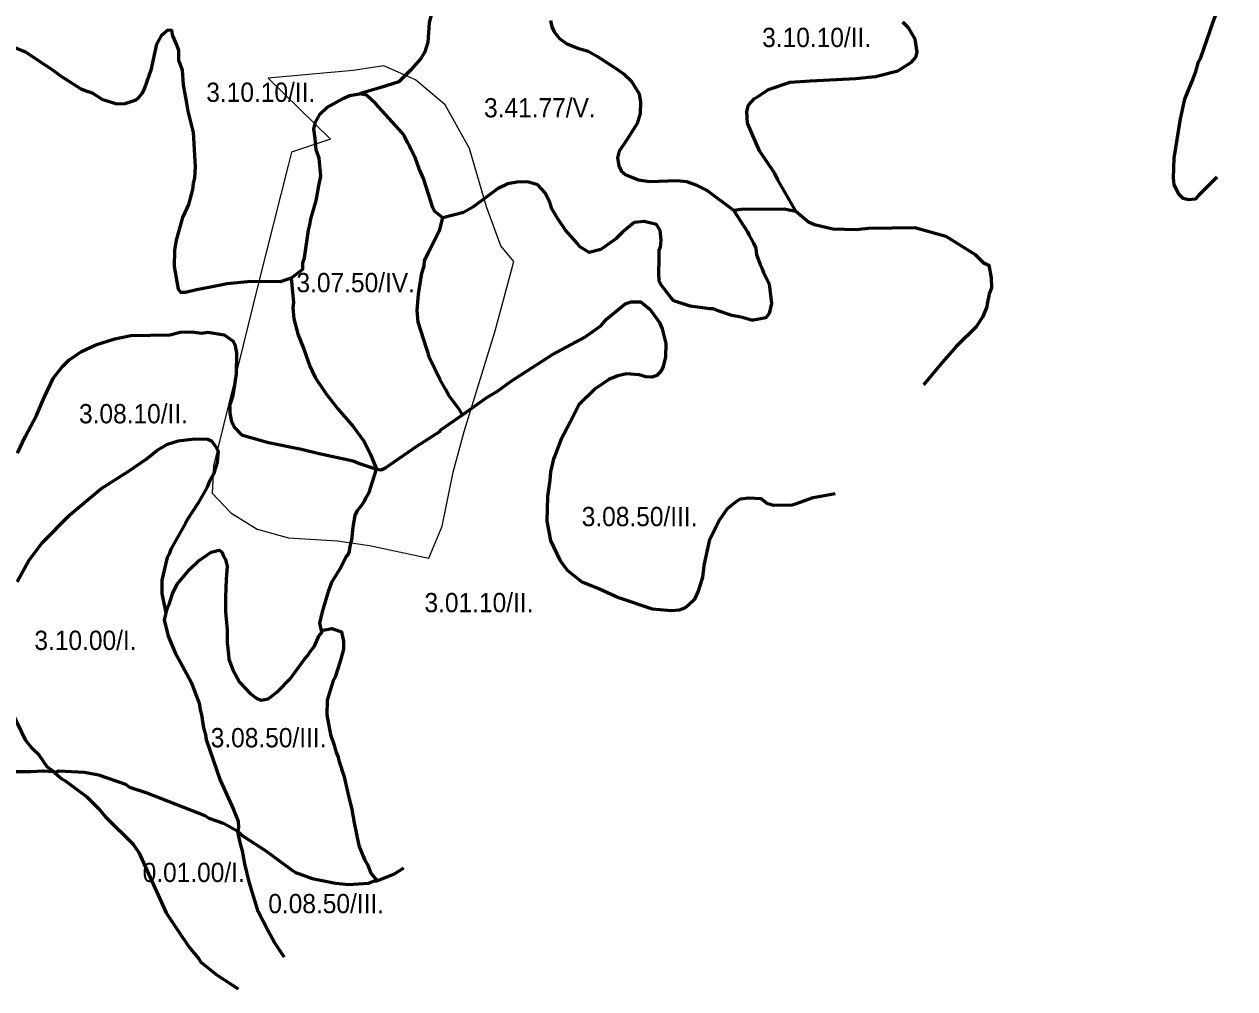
# Model space of a CAD drawing. Extents: x -555506 to -553028, y -1186750 to -1182668.
# Drawn here: x -554397 to -553142, y -1186750 to -1185749 of the extents above; entities that cross this region are included whole.
import ezdxf
from ezdxf.enums import TextEntityAlignment as Align

# ---------------------------------------------------------------- set-up
doc = ezdxf.new("R2010")
doc.units = 0
doc.header["$LTSCALE"] = 8
doc.layers.add('21', color=7, linetype='Continuous', lineweight=53)
doc.layers.add('41', color=7, linetype='Continuous', lineweight=25)
doc.layers.add('22', color=7, linetype='Continuous')

msp = doc.modelspace()

# ---------------------------------------------------------------- linework, layer by layer
at = {"layer": '21'}
msp.add_line((-554365.314, -1186526.02), (-554366.937, -1186524.625), dxfattribs=at)
for points in [[(-553945.125, -1185676.626), (-553945.937, -1185701.626), (-553947.625, -1185708.376), (-553952.75, -1185718.625), (-553963.75, -1185728.75), (-553971.375, -1185733.876), (-553974.375, -1185737.25), (-553977.312, -1185747.375), (-553978.625, -1185767.751), (-553981.562, -1185778), (-553985.812, -1185784.751), (-553996.375, -1185796.625), (-554003.187, -1185803.376), (-554008.687, -1185808.875), (-554027.375, -1185814.876), (-554049.375, -1185821.626)], [(-553160.224, -1185907.948), (-553179, -1185926.75), (-553182.812, -1185930.625), (-553189.562, -1185931.5), (-553195.062, -1185930.125), (-553199.75, -1185925.501), (-553204.437, -1185915.376), (-553205.25, -1185908.5), (-553204.437, -1185888.25), (-553198.062, -1185847.5), (-553193.375, -1185827.126), (-553185.75, -1185808.501), (-553181.937, -1185798.25), (-553179.375, -1185788.125), (-553177.312, -1185784.751), (-553163.687, -1185745.75), (-553151, -1185711.875), (-553145.5, -1185700.001), (-553141.687, -1185689.376)], [(-554120.187, -1186012.876), (-554131.625, -1186016.626), (-554162.187, -1186016.25), (-554186.75, -1186018.751), (-554204.125, -1186022.125), (-554218.562, -1186024.75), (-554230, -1186027.625), (-554234.687, -1186027.625), (-554237.25, -1186024.25), (-554241.437, -1186000.5), (-554241.062, -1185983.626), (-554239.375, -1185973.376), (-554232.562, -1185949.625), (-554226.625, -1185936.126), (-554222.375, -1185920.875), (-554221.562, -1185914.001), (-554220.25, -1185909.001), (-554219.437, -1185897.125), (-554221.562, -1185861.501), (-554227.062, -1185839.376), (-554228.75, -1185829.251), (-554232.125, -1185812.251), (-554233, -1185797.001), (-554236.812, -1185786.876), (-554236.812, -1185776.625), (-554239.375, -1185769.876), (-554243.187, -1185761.376), (-554244, -1185755.875), (-554248.25, -1185755.501), (-554255.062, -1185761.376), (-554260.125, -1185769.876), (-554266.062, -1185797.001), (-554272.437, -1185815.751), (-554274.937, -1185820.751), (-554279.187, -1185825.876), (-554281.312, -1185828.001), (-554292.75, -1185831.751), (-554301.25, -1185832.251), (-554315.687, -1185827.626), (-554326.25, -1185820.751), (-554333.875, -1185818.25), (-554338.125, -1185816.501), (-554359.312, -1185803), (-554366.125, -1185797.876), (-554395.375, -1185778.376), (-554422.937, -1185767.375)], [(-553851.375, -1185745.25), (-553850.125, -1185752.125), (-553847.562, -1185757.126), (-553842.062, -1185764.001), (-553834.437, -1185769.5), (-553823, -1185774.126), (-553812.375, -1185777.126), (-553802.625, -1185782.626), (-553786.937, -1185792.751), (-553775.062, -1185801.25), (-553767.875, -1185808.001), (-553759.375, -1185821.626), (-553758.125, -1185830.126), (-553758.562, -1185842), (-553761.5, -1185852.125), (-553772.125, -1185869.125), (-553780.187, -1185881.001), (-553781.875, -1185887.75), (-553780.625, -1185896.25), (-553778.062, -1185901.375), (-553773.375, -1185905.625), (-553760.25, -1185910.626), (-553748.812, -1185912.376), (-553720.375, -1185911.5), (-553710.25, -1185912.376), (-553700.5, -1185915.75), (-553689, -1185921.625), (-553661.437, -1185942.001)], [(-553597, -1185943.25), (-553615.687, -1185910.626), (-553618.625, -1185904.25), (-553634.75, -1185880.501), (-553647.062, -1185851.75), (-553647.875, -1185839.875), (-553646.187, -1185833.125), (-553639.812, -1185826.25), (-553636.875, -1185824.625), (-553625.437, -1185817.001), (-553602.937, -1185809.375), (-553581.75, -1185808.001), (-553534.687, -1185805.5), (-553514.375, -1185803.376), (-553491, -1185797.5), (-553487.187, -1185795.375), (-553477.062, -1185788.501), (-553472.375, -1185783.501), (-553471.125, -1185778.376), (-553473.25, -1185764.876), (-553480, -1185753), (-553485.937, -1185747.001)], [(-554120.187, -1186012.876), (-554108.312, -1186003.501), (-554108.312, -1185996.75), (-554106.625, -1185991.626), (-554102.375, -1185962.751), (-554100.687, -1185956), (-554100.25, -1185952.626), (-554094.375, -1185932.25), (-554091.812, -1185917.001), (-554089.687, -1185906.876), (-554091.375, -1185888.25), (-554094.375, -1185879.75), (-554095.625, -1185867.876), (-554096.875, -1185857.625), (-554095.187, -1185850.876), (-554090.125, -1185842.376), (-554083.312, -1185835.626), (-554066.375, -1185826.25), (-554060, -1185823.376), (-554049.375, -1185821.626)], [(-553962.937, -1185950.125), (-553971.812, -1185943.25), (-553973.5, -1185939.876), (-553983.25, -1185909.375), (-553987.5, -1185899.25), (-553991.75, -1185887.376), (-553996.375, -1185878.876), (-553997.687, -1185875.5), (-553999.812, -1185872.126), (-554002.75, -1185865.251), (-554005.312, -1185861.875), (-554032.875, -1185831.376), (-554042.187, -1185822.876), (-554049.375, -1185821.626)], [(-553661.437, -1185942.001), (-553647.062, -1185964.5), (-553645.75, -1185967.876), (-553640.687, -1185976.376), (-553638.562, -1185981.501), (-553637.75, -1185988.25), (-553633.875, -1185998.375), (-553632.187, -1186001.875), (-553630.5, -1186006.875), (-553624.562, -1186018.751), (-553622.062, -1186039.125), (-553624.562, -1186049.25), (-553628, -1186054), (-553640.687, -1186056.125), (-553642.812, -1186056.125), (-553653.812, -1186053.126), (-553663.187, -1186051.375), (-553677.562, -1186046.751), (-553682.687, -1186044.626), (-553686.062, -1186044.626), (-553706.375, -1186041.626), (-553723.375, -1186036.125), (-553726.75, -1186032.75), (-553736.937, -1186019.251), (-553738.625, -1186015.751), (-553739.062, -1186007.375), (-553738.625, -1185993.751), (-553738.625, -1185983.626), (-553737.375, -1185980.25), (-553736.5, -1185973.376), (-553737.75, -1185963.25), (-553741.625, -1185956.876), (-553754.312, -1185953.875), (-553764.5, -1185955.125), (-553776.812, -1185964.876), (-553783.562, -1185971.75), (-553795.437, -1185980.25), (-553799.25, -1185983.125), (-553811.125, -1185986.125), (-553821.312, -1185979.75), (-553823.875, -1185976.376), (-553835.75, -1185962.751), (-553843.75, -1185951.001), (-553850.125, -1185940.75), (-553852.25, -1185934.001), (-553857.312, -1185923.75), (-553864.562, -1185915.75), (-553875.125, -1185912.751), (-553886.187, -1185913.251), (-553895.5, -1185914.876), (-553906.5, -1185920), (-553931.937, -1185939.126), (-553941.687, -1185944.626), (-553962.937, -1185950.125)], [(-553661.437, -1185942.001), (-553653.812, -1185941.251), (-553608.875, -1185940.75), (-553597, -1185943.25)], [(-553597, -1185943.25), (-553583.875, -1185954.375), (-553577.5, -1185956.876), (-553558.437, -1185961.501), (-553533.875, -1185962.375), (-553521.562, -1185960.75), (-553473.625, -1185960.25), (-553441.437, -1185969.126), (-553410.875, -1185988.25), (-553402.437, -1185996.75), (-553396.875, -1185999.251), (-553394.375, -1186012.376), (-553393.937, -1186022.625), (-553396.5, -1186029.376), (-553398.625, -1186039.501), (-553399, -1186042.501), (-553403.25, -1186053.126), (-553410.062, -1186063.251), (-553430.812, -1186083.625), (-553447.173, -1186102.559), (-553464.42, -1186123.36)], [(-553942.562, -1186154.5), (-553945.5, -1186149.75), (-553957, -1186134.5), (-553960.375, -1186127.751), (-553966.312, -1186117.626), (-553976.875, -1186095.501), (-553978.187, -1186090.376), (-553979.875, -1186085.376), (-553988.75, -1186058.25), (-553989.625, -1186046.375), (-553988.375, -1186029.376), (-553984.937, -1186007.375), (-553982.437, -1185999.75), (-553982, -1185994.625), (-553977.75, -1185986.125), (-553966.312, -1185962.375), (-553962.937, -1185950.125)], [(-554120.187, -1186012.876), (-554118.062, -1186037.876), (-554118.5, -1186043.001), (-554117.687, -1186054.875), (-554113, -1186071.751), (-554107.5, -1186085.376), (-554101.125, -1186104.001), (-554095.625, -1186115.875), (-554084.187, -1186132.875), (-554071.875, -1186148.125), (-554056.187, -1186166.75), (-554044.75, -1186182), (-554037.937, -1186195.626), (-554032, -1186210.876)], [(-553942.562, -1186154.5), (-553917.562, -1186136.625), (-553906.5, -1186129.876), (-553892.125, -1186119.625), (-553849.312, -1186091.751), (-553815.812, -1186073.876), (-553799.25, -1186062), (-553793.312, -1186055.251), (-553773.812, -1186039.501), (-553767.875, -1186037.376), (-553757.687, -1186037.376), (-553747.937, -1186045.126), (-553738.187, -1186058.625), (-553735.687, -1186065.376), (-553731.875, -1186080.625), (-553732.25, -1186094.25), (-553734.375, -1186104.375), (-553736.937, -1186109.5), (-553741.187, -1186113.75), (-553746.25, -1186115.501), (-553752.625, -1186115), (-553759.375, -1186112.875), (-553772.562, -1186112.001), (-553781.437, -1186114.126), (-553790.75, -1186118), (-553805.187, -1186127.375), (-553822.125, -1186144.251), (-553827.25, -1186154.5), (-553830.625, -1186161.251), (-553840.375, -1186179.876), (-553846.75, -1186196.875), (-553848.437, -1186200.251), (-553851.375, -1186213.751), (-553852.25, -1186222.251), (-553854.375, -1186239.25), (-553855.25, -1186264.626), (-553851.375, -1186285), (-553841.625, -1186305.376), (-553834, -1186315.5), (-553818.75, -1186327.876), (-553800.5, -1186335.125), (-553781, -1186344), (-553745.812, -1186355.875), (-553726.312, -1186357.5), (-553717.437, -1186356.626), (-553711.937, -1186354.625), (-553708.125, -1186351.625), (-553701.312, -1186344.876), (-553698.375, -1186338.001), (-553693.25, -1186322.751), (-553692, -1186310.875), (-553686.062, -1186283.75), (-553679.687, -1186270.251), (-553676.312, -1186264.25), (-553667.812, -1186251.5), (-553657.625, -1186243.876), (-553654.25, -1186241.751), (-553645.75, -1186240.5), (-553633.062, -1186241.375), (-553627.125, -1186246.001), (-553619.937, -1186248.126), (-553600.812, -1186247.75), (-553596.187, -1186246.501), (-553578.812, -1186240.126), (-553556.1, -1186236.222)], [(-554404.25, -1186194.25), (-554396.187, -1186177.375), (-554384.375, -1186155.25), (-554376.687, -1186136.625), (-554366.937, -1186116.251), (-554360.187, -1186107.751), (-554357.625, -1186104.375), (-554350.875, -1186097.626), (-554337.687, -1186088.75), (-554322.875, -1186082), (-554303.375, -1186075.625), (-554286.812, -1186072.251), (-554246.125, -1186071.375), (-554235.5, -1186068.75), (-554223.25, -1186068.375), (-554213.062, -1186069.626), (-554206.687, -1186068.75), (-554189.75, -1186071.375), (-554180.437, -1186078.126), (-554178.687, -1186081.5), (-554177, -1186090), (-554177.437, -1186112.001), (-554179.562, -1186125.626), (-554181.25, -1186135.751), (-554184.25, -1186145.125), (-554183.812, -1186147.625), (-554183.812, -1186152.751), (-554182.125, -1186161.251), (-554178.687, -1186168.001), (-554171.937, -1186175.25), (-554143.937, -1186183.25), (-554109.625, -1186190.126), (-554091.375, -1186194.75), (-554056.187, -1186202.376), (-554049.375, -1186204.875), (-554032, -1186210.876)], [(-554032, -1186210.876), (-554026.937, -1186211.626), (-554022.687, -1186209.625), (-553990.062, -1186187.126), (-553966.312, -1186171.875), (-553965.062, -1186170.126), (-553942.562, -1186154.5)], [(-554404.687, -1186327.876), (-554392.375, -1186305.751), (-554378.437, -1186287.125), (-554350, -1186258.375), (-554317.75, -1186231.25), (-554288.5, -1186212.501), (-554270.75, -1186200.625), (-554259.687, -1186191.376), (-554248.687, -1186185.001), (-554237.625, -1186181.625), (-554220.25, -1186179.5), (-554206.687, -1186179.876), (-554202.875, -1186181.625), (-554200.312, -1186185.375), (-554197.812, -1186188.751), (-554196.125, -1186192.125), (-554196.937, -1186204), (-554200.75, -1186215.876), (-554204.562, -1186222.75), (-554207.562, -1186229.501), (-554217.312, -1186246.501), (-554228.312, -1186263.376), (-554230, -1186266.751), (-554245.25, -1186294.001), (-554247, -1186299.001), (-554249.125, -1186302.375), (-554254.625, -1186326.125), (-554254.625, -1186339.75), (-554250.294, -1186360.186)], [(-554088.812, -1186378.25), (-554090.5, -1186370.625), (-554088, -1186358.751), (-554081.187, -1186336.75), (-554078.25, -1186328.25), (-554069.75, -1186314.751), (-554063, -1186301.126), (-554061.25, -1186299.5), (-554060, -1186296), (-554059.125, -1186291.001), (-554057.437, -1186284.126), (-554056.187, -1186270.625), (-554054.062, -1186258.751), (-554051.5, -1186253.625), (-554047.312, -1186248.626), (-554043.875, -1186243.5), (-554042.625, -1186240.126), (-554039.625, -1186235), (-554032, -1186210.876)], [(-554250.294, -1186360.186), (-554248.25, -1186353.75), (-554246.562, -1186350.375), (-554243.562, -1186340.126), (-554238.5, -1186330.001), (-554225.375, -1186314.751), (-554216.875, -1186306.251), (-554203.312, -1186296.876), (-554195.187, -1186294.751), (-554192.125, -1186296.5), (-554190.562, -1186301.126), (-554188.5, -1186304.5), (-554186.75, -1186311.375), (-554187.625, -1186324.876), (-554188.5, -1186343.501), (-554188.5, -1186352), (-554188.5, -1186358.751), (-554186.75, -1186377.5), (-554186.75, -1186391.001), (-554185.5, -1186402.875), (-554185.062, -1186408.001), (-554180.437, -1186419.875), (-554174.062, -1186431.751), (-554163, -1186443.625), (-554155.812, -1186448.751), (-554151.562, -1186450.376), (-554144.375, -1186449.126), (-554141.375, -1186447), (-554134.187, -1186441.5), (-554121.5, -1186428.375), (-554106.625, -1186408.001), (-554103.25, -1186404.626), (-554100.25, -1186399.501), (-554096.062, -1186394.376), (-554091.812, -1186384.251), (-554088.437, -1186380.376), (-554088.812, -1186378.25)], [(-554250.294, -1186360.186), (-554251.187, -1186363.001), (-554252.062, -1186367.251), (-554247.812, -1186384.251), (-554240.625, -1186401.25), (-554235.125, -1186411.375), (-554224.062, -1186431.751), (-554215.625, -1186453.75), (-554214.75, -1186460.501), (-554213.5, -1186465.626), (-554211.375, -1186479.25), (-554209.25, -1186486), (-554208.375, -1186491.126), (-554194, -1186533.501), (-554180, -1186564), (-554175.312, -1186575.876), (-554174.875, -1186582.625), (-554175.75, -1186586.876)], [(-554088.812, -1186378.25), (-554078.25, -1186376.25), (-554068.062, -1186379.625), (-554065.937, -1186389.376), (-554065.937, -1186397.75), (-554067.625, -1186402.875), (-554069.75, -1186411.375), (-554074.812, -1186426.626), (-554076.937, -1186430), (-554082.875, -1186450.376), (-554083.312, -1186465.626), (-554079.5, -1186486), (-554076.125, -1186496.125), (-554073.562, -1186504.625), (-554071.437, -1186509.751), (-554071, -1186513.125), (-554065.5, -1186530.126), (-554061.687, -1186547), (-554057.437, -1186564), (-554054.937, -1186577.625), (-554050.25, -1186601.375), (-554046, -1186611.5), (-554043.875, -1186616.626), (-554040.937, -1186621.625), (-554037.562, -1186630.125), (-554031.187, -1186637.751)], [(-554643.812, -1186442.376), (-554631.5, -1186459.751), (-554617.562, -1186471.625), (-554610.75, -1186475.875), (-554573.875, -1186495.376), (-554538.25, -1186510.126), (-554515.75, -1186517.001), (-554492.062, -1186519.876), (-554453, -1186521.625), (-554411.062, -1186524.625), (-554390.25, -1186524.625), (-554377.562, -1186523.75), (-554366.937, -1186524.625)], [(-554366.937, -1186524.625), (-554373.312, -1186519.5), (-554381.812, -1186507.626), (-554388.562, -1186500.875), (-554395.375, -1186492.375), (-554409.375, -1186463.501)], [(-554175.75, -1186586.876), (-554190.562, -1186578.375), (-554205.437, -1186573.375), (-554209.687, -1186570.375), (-554269.875, -1186547), (-554287.687, -1186541.125), (-554291.937, -1186538.125), (-554319.875, -1186528.375), (-554335.187, -1186525.375), (-554361.437, -1186524.125), (-554365.314, -1186526.02)], [(-554365.314, -1186526.02), (-554358.062, -1186532.251), (-554355.062, -1186533.875), (-554332.187, -1186550.876), (-554320.312, -1186562.75), (-554313.125, -1186571.25), (-554284.312, -1186600), (-554278.375, -1186608.5), (-554249.937, -1186671.251), (-554237.625, -1186689.876), (-554226.187, -1186706.875), (-554216, -1186718.751), (-554213.875, -1186722.126), (-554196.937, -1186735.751), (-554175.471, -1186749.91)], [(-554175.75, -1186586.876), (-554168.937, -1186592.376), (-554146.5, -1186606.875), (-554118.937, -1186627.125), (-554116, -1186629.25), (-554111.75, -1186630.625), (-554098.562, -1186635.626), (-554074.437, -1186640.376), (-554060.875, -1186641.625), (-554040.062, -1186640.376), (-554035, -1186638.251), (-554031.187, -1186637.751)], [(-554127.145, -1186717.191), (-554128.687, -1186715.375), (-554137.562, -1186701.75), (-554144.375, -1186689.876), (-554154.562, -1186669.626), (-554163.875, -1186639.001), (-554168.562, -1186620.376), (-554170.687, -1186606.875), (-554171.937, -1186603.5), (-554173.625, -1186596.626), (-554175.75, -1186586.876)], [(-554003.682, -1186624.864), (-554013.375, -1186631.001), (-554029.062, -1186637.376), (-554031.187, -1186637.751)]]:
    msp.add_lwpolyline(points, dxfattribs=at)
at = {"layer": '41'}
for points in [[(-554182.983, -1186256.105), (-554155.475, -1186273.104), (-554123.112, -1186282.008), (-554072.141, -1186285.246), (-554038.97, -1186290.103), (-553977.481, -1186303.054), (-553963.727, -1186269.866), (-553952.4, -1186214.013), (-553941.073, -1186171.921), (-553908.711, -1186067.5), (-553889.293, -1185995.458), (-553903.047, -1185979.269), (-553917.61, -1185938.796), (-553935.41, -1185878.086), (-553960.491, -1185832.756), (-553991.235, -1185806.854), (-554024.407, -1185792.283), (-554055.96, -1185797.14), (-554144.148, -1185805.235), (-554079.423, -1185868.373), (-554119.876, -1185882.134), (-554123.112, -1185894.276), (-554154.665, -1186018.933), (-554200.782, -1186207.537)], [(-554200.782, -1186207.537), (-554202.4, -1186235.869), (-554182.983, -1186256.105)]]:
    msp.add_lwpolyline(points, dxfattribs=at)

# ---------------------------------------------------------------- texts
at = {"layer": '22', "width": 0.95}
for s, p in [('3.10.10/II.', (-553575.364, -1185772.946)), ('3.10.10/II.', (-554151.868, -1185829.837)), ('3.41.77/V.', (-553862.407, -1185845.924)), ('3.07.50/IV.', (-554053.402, -1186027.286)), ('3.08.10/II.', (-554283.88, -1186163.297)), ('3.08.50/III.', (-553758.97, -1186270.005)), ('3.01.10/II.', (-553925.583, -1186359.255)), ('3.10.00/I.', (-554333.672, -1186398.416)), ('3.08.50/III.', (-554143.773, -1186499.408)), ('0.01.00/I.', (-554221.424, -1186639.159)), ('0.08.50/III.', (-554084.06, -1186671.507))]:
    msp.add_text(s, height=20, dxfattribs=at).set_placement(p, align=Align.CENTER)

doc.saveas('drawing.dxf')
